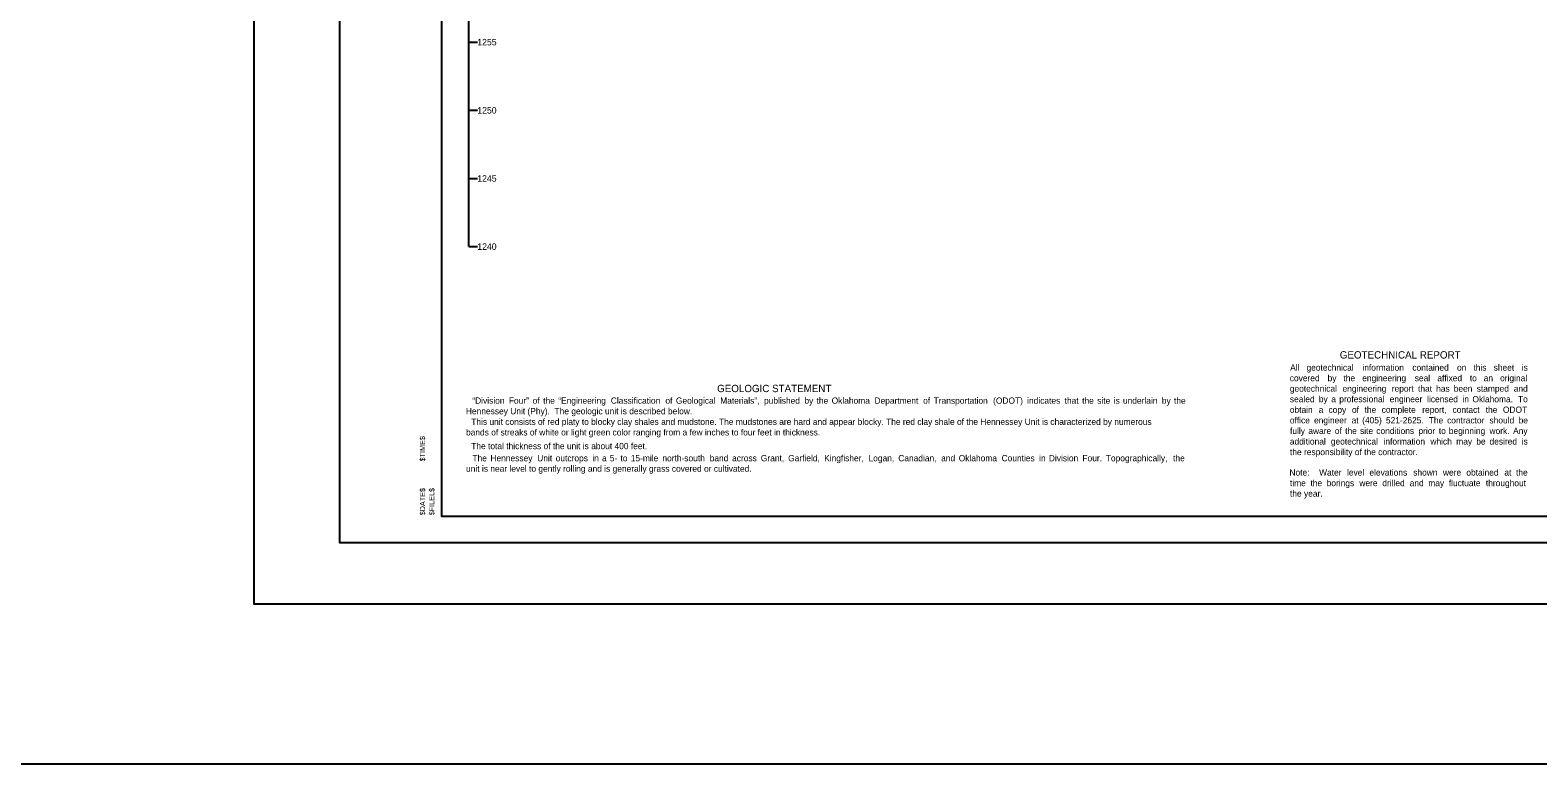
# Model space of a CAD drawing. Extents: x -2 to 138, y 24 to 58.
# Drawn here: x 85.7 to 114.52, y 26.92 to 40.94 of the extents above; entities that cross this region are included whole.
import ezdxf

# ---------------------------------------------------------------- set-up
doc = ezdxf.new("R2010")
doc.units = 0
for name, color, linetype in [('S', 7, 'Continuous'), ('SHT_Plot_Shape_Full', 7, 'Continuous'), ('SHT_Plot_Shape_Half', 7, 'Continuous'), ('SHT_Plot_Stamp', 7, 'Continuous'), ('SHT_Sheet_Border', 7, 'Continuous'), ('Text', 7, 'Continuous')]:
    doc.layers.add(name, color=color, linetype=linetype)

# ---------------------------------------------------------------- blocks, each defined once
blk = doc.blocks.new('Stamp_Plot_Stamp')
at = {"layer": 'SHT_Plot_Stamp'}
for s, p in [('$TIME$', (1.695, 1.572)), ('$DATE$', (1.695, 0.542)), ('$FILEL$', (1.873, 0.542))]:
    blk.add_text(s, height=0.1, rotation=90, dxfattribs=at).set_placement(p)

msp = doc.modelspace()

# ---------------------------------------------------------------- linework, layer by layer
msp.add_line((94.084, 36.804), (94.084, 49.825))
for points in [[(94.084, 40.711), (94.251, 40.711)], [(94.084, 39.408), (94.251, 39.408)], [(94.084, 38.106), (94.251, 38.106)], [(94.084, 36.804), (94.251, 36.804)]]:
    msp.add_lwpolyline(points)
at = {"layer": 'S'}
msp.add_lwpolyline([(-2.212, 26.92), (137.529, 26.92), (137.529, 58.049), (-2.212, 58.049)], close=True, dxfattribs=at)
at = {"layer": 'SHT_Plot_Shape_Full'}
msp.add_lwpolyline([(89.979, 53.971), (125.979, 53.971), (125.979, 29.971), (89.979, 29.971)], close=True, dxfattribs=at)
at = {"layer": 'SHT_Plot_Shape_Half'}
msp.add_lwpolyline([(91.616, 53.146), (125.616, 53.146), (125.616, 31.146), (91.616, 31.146)], close=True, dxfattribs=at)
at = {"layer": 'SHT_Sheet_Border'}
msp.add_lwpolyline([(93.566, 52.646), (125.066, 52.646), (125.066, 31.646), (93.566, 31.646)], close=True, dxfattribs=at)

# ---------------------------------------------------------------- block references
at = {"layer": 'SHT_Plot_Stamp'}
msp.add_blockref('Stamp_Plot_Stamp', (91.553, 31.127), dxfattribs=at)

# ---------------------------------------------------------------- texts
for s, p in [('1255', (94.246, 40.649)), ('1250', (94.246, 39.346)), ('1245', (94.246, 38.044)), ('1240', (94.246, 36.742))]:
    msp.add_text(s, height=0.124).set_placement(p)
at = {"layer": 'Text'}
for s, height, p in [('GEOTECHNICAL REPORT', 0.14, (110.732, 34.665)), ('All', 0.12, (109.783, 34.433)), ('covered', 0.12, (109.776, 34.231)), ('geotechnical', 0.12, (110.096, 34.433)), ('by', 0.12, (110.499, 34.231)), ('the', 0.12, (110.802, 34.231)), ('engineering', 0.12, (111.161, 34.231)), ('information', 0.12, (111.164, 34.433)), ('contained', 0.12, (112.119, 34.433)), ('seal', 0.12, (112.164, 34.231)), ('affixed', 0.12, (112.597, 34.231)), ('on', 0.12, (112.973, 34.433)), ('to', 0.12, (113.217, 34.231)), ('this', 0.12, (113.286, 34.433)), ('an', 0.12, (113.483, 34.231)), ('sheet', 0.12, (113.673, 34.433)), ('original ', 0.12, (113.796, 34.231)), ('is ', 0.12, (114.21, 34.433)), ('GEOLOGIC STATEMENT', 0.14, (98.83, 34.023)), ('geotechnical', 0.12, (109.777, 34.031)), ('engineering', 0.12, (110.784, 34.031)), ('report', 0.12, (111.726, 34.031)), ('that', 0.12, (112.229, 34.031)), ('has', 0.12, (112.574, 34.031)), ('been', 0.12, (112.91, 34.031)), ('stamped', 0.12, (113.349, 34.031)), ('and ', 0.12, (114.057, 34.031)), ('Hennessey Unit (Phy).  The geologic unit is described below.', 0.12, (94.028, 33.599)), ('“Division', 0.12, (94.151, 33.801)), ('Four”', 0.12, (94.849, 33.801)), ('of', 0.12, (95.304, 33.801)), ('the', 0.12, (95.505, 33.801)), ('“Engineering', 0.12, (95.793, 33.801)), ('Classification', 0.12, (96.798, 33.801)), ('of', 0.12, (97.841, 33.801)), ('Geological', 0.12, (98.042, 33.801)), ('Materials”,', 0.12, (98.889, 33.801)), ('published', 0.12, (99.726, 33.801)), ('by', 0.12, (100.499, 33.801)), ('the', 0.12, (100.731, 33.801)), ('Oklahoma', 0.12, (101.019, 33.801)), ('Department', 0.12, (101.838, 33.801)), ('of', 0.12, (102.768, 33.801)), ('Transportation', 0.12, (102.969, 33.801)), ('(ODOT)', 0.12, (104.105, 33.801)), ('indicates', 0.12, (104.756, 33.801)), ('that', 0.12, (105.472, 33.801)), ('the', 0.12, (105.807, 33.801)), ('site', 0.12, (106.095, 33.801)), ('is', 0.12, (106.411, 33.801)), ('underlain', 0.12, (106.587, 33.801)), ('by', 0.12, (107.331, 33.801)), ('the ', 0.12, (107.563, 33.801)), ('sealed', 0.12, (109.778, 33.829)), ('obtain', 0.12, (109.777, 33.627)), ('a', 0.12, (110.329, 33.627)), ('by', 0.12, (110.332, 33.829)), ('copy', 0.12, (110.516, 33.627)), ('a', 0.12, (110.569, 33.829)), ('professional', 0.12, (110.722, 33.829)), ('of', 0.12, (110.965, 33.627)), ('the', 0.12, (111.205, 33.627)), ('complete', 0.12, (111.533, 33.627)), ('engineer', 0.12, (111.686, 33.829)), ('report,', 0.12, (112.308, 33.627)), ('licensed', 0.12, (112.401, 33.829)), ('contact', 0.12, (112.887, 33.627)), ('in', 0.12, (113.076, 33.829)), ('Oklahoma.', 0.12, (113.267, 33.829)), ('the', 0.12, (113.522, 33.627)), ('ODOT ', 0.12, (113.85, 33.627)), ('To ', 0.12, (114.138, 33.829)), ('  This unit consists of red platy to blocky clay shales and mudstone. The mudstones are hard and appear blocky. The red clay shale of the Hennessey Unit is characterized by numerous ', 0.12, (94.041, 33.397)), ('office', 0.12, (109.777, 33.425)), ('engineer', 0.12, (110.24, 33.425)), ('at', 0.12, (110.958, 33.425)), ('(405)', 0.12, (111.16, 33.425)), ('521-2625.', 0.12, (111.614, 33.425)), ('The', 0.12, (112.432, 33.425)), ('contractor', 0.12, (112.783, 33.425)), ('should', 0.12, (113.593, 33.425)), ('be ', 0.12, (114.15, 33.425)), ('bands of streaks of white or light green color ranging from a few inches to four feet in thickness.', 0.12, (94.03, 33.195)), ('fully', 0.12, (109.781, 33.223)), ('additional', 0.12, (109.777, 33.021)), ('aware', 0.12, (110.13, 33.223)), ('geotechnical', 0.12, (110.561, 33.021)), ('of', 0.12, (110.638, 33.223)), ('the', 0.12, (110.835, 33.223)), ('site', 0.12, (111.119, 33.223)), ('conditions', 0.12, (111.43, 33.223)), ('information', 0.12, (111.568, 33.021)), ('prior', 0.12, (112.236, 33.223)), ('which', 0.12, (112.464, 33.021)), ('to', 0.12, (112.625, 33.223)), ('beginning', 0.12, (112.816, 33.223)), ('be', 0.12, (113.341, 33.021)), ('work.', 0.12, (113.594, 33.223)), ('desired', 0.12, (113.594, 33.021)), ('Any ', 0.12, (114.045, 33.223)), ('is ', 0.12, (114.21, 33.021)), ('  The total thickness of the unit is about 400 feet.', 0.12, (94.041, 32.933)), ('the responsibility of the contractor.', 0.12, (109.78, 32.819)), ('may', 0.12, (112.958, 33.021)), ('unit is near level to gently rolling and is generally grass covered or cultivated.  ', 0.12, (94.031, 32.501)), ('The', 0.12, (94.153, 32.701)), ('Hennessey', 0.12, (94.497, 32.701)), ('Unit', 0.12, (95.391, 32.701)), ('outcrops', 0.12, (95.745, 32.701)), ('in', 0.12, (96.444, 32.701)), ('a', 0.12, (96.63, 32.701)), ('5-', 0.12, (96.779, 32.701)), ('to', 0.12, (96.983, 32.701)), ('15-mile', 0.12, (97.179, 32.701)), ('north-south', 0.12, (97.784, 32.701)), ('band', 0.12, (98.688, 32.701)), ('across', 0.12, (99.116, 32.701)), ('Grant,', 0.12, (99.666, 32.701)), ('Garfield,', 0.12, (100.187, 32.701)), ('Kingfisher,', 0.12, (100.876, 32.701)), ('Logan,', 0.12, (101.724, 32.701)), ('Canadian,', 0.12, (102.292, 32.701)), ('and', 0.12, (103.112, 32.701)), ('Oklahoma', 0.12, (103.448, 32.701)), ('Counties', 0.12, (104.267, 32.701)), ('in', 0.12, (104.985, 32.701)), ('Division', 0.12, (105.171, 32.701)), ('Four.', 0.12, (105.813, 32.701)), ('Topographically,', 0.12, (106.26, 32.701)), ('the ', 0.12, (107.546, 32.701)), ('time', 0.12, (109.78, 32.226)), ('Note:', 0.12, (109.77, 32.428)), ('the', 0.12, (110.172, 32.226)), ('Water', 0.12, (110.337, 32.428)), ('borings', 0.12, (110.481, 32.226)), ('level', 0.12, (110.87, 32.428)), ('were', 0.12, (111.106, 32.226)), ('elevations', 0.12, (111.298, 32.428)), ('drilled', 0.12, (111.545, 32.226)), ('and', 0.12, (112.068, 32.226)), ('shown', 0.12, (112.136, 32.428)), ('may', 0.12, (112.423, 32.226)), ('were', 0.12, (112.704, 32.428)), ('fluctuate', 0.12, (112.815, 32.226)), ('obtained', 0.12, (113.151, 32.428)), ('throughout ', 0.12, (113.524, 32.226)), ('at', 0.12, (113.878, 32.428)), ('the ', 0.12, (114.101, 32.428)), ('the year.', 0.12, (109.78, 32.026))]:
    msp.add_text(s, height=height, dxfattribs=at).set_placement(p)

doc.saveas('drawing.dxf')
